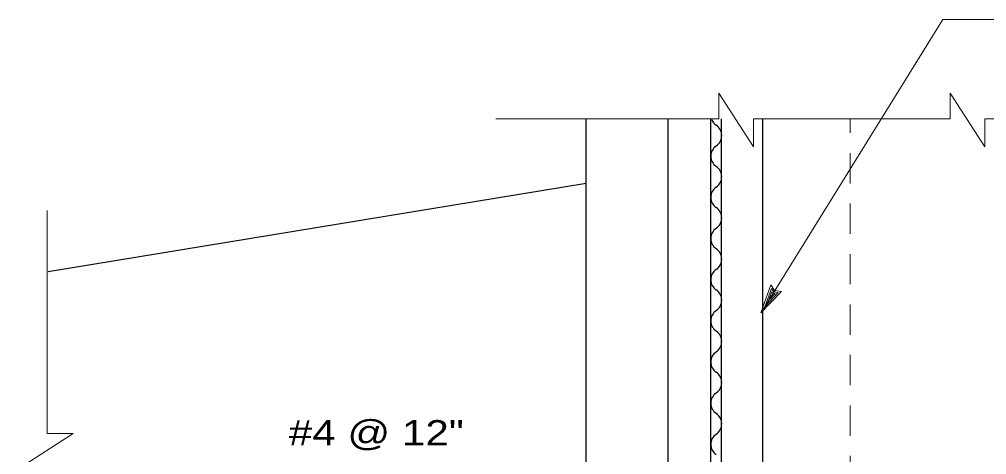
# Model space of a CAD drawing. Extents: x -28.1 to 13.9, y -16.1 to 13.9.
# Drawn here: x -24.101 to -19.308, y -3.215 to -1.058 of the extents above; entities that cross this region are included whole.
import ezdxf
from ezdxf.enums import TextEntityAlignment as Align

# ---------------------------------------------------------------- set-up
doc = ezdxf.new("R2010")
doc.units = 0
doc.header["$LTSCALE"] = 0.05
doc.linetypes.add('MEDIUM_DASHED', pattern=[4.5, 3, -1.5])
doc.layers.add('1', color=7, linetype='Continuous', lineweight=13)

msp = doc.modelspace()

# ---------------------------------------------------------------- linework, layer by layer
at = {"layer": '1'}
for p, q in [((-20.63504, -1.55131), (-20.63504, -1.42331)), ((-20.46304, -1.68931), (-20.63504, -1.42331)), ((-19.48904, -1.55131), (-19.48904, -1.42331)), ((-19.31704, -1.68931), (-19.48904, -1.42331)), ((-20.63504, -1.55131), (-21.74004, -1.55131)), ((-20.46304, -1.68931), (-20.46304, -1.55131)), ((-19.48904, -1.55131), (-20.46304, -1.55131)), ((-19.31704, -1.68931), (-19.31704, -1.55131)), ((-18.25304, -1.55131), (-19.31704, -1.55131)), ((-23.96304, -3.11031), (-23.96304, -2.00531)), ((-20.42704, -2.51331), (-20.37804, -2.37431)), ((-20.40804, -2.48231), (-20.37504, -2.39131)), ((-20.37504, -2.39131), (-20.36304, -2.40931)), ((-20.42704, -2.51331), (-20.32504, -2.40731)), ((-20.40804, -2.48231), (-20.34104, -2.41231)), ((-20.38904, -2.45131), (-20.37304, -2.40731)), ((-20.38904, -2.45131), (-20.35704, -2.41731)), ((-20.37304, -2.40731), (-20.36704, -2.41631)), ((-20.36704, -2.41631), (-20.35704, -2.41731)), ((-20.36304, -2.40931), (-20.34104, -2.41231)), ((-24.10104, -3.28231), (-23.83504, -3.11031)), ((-23.96304, -3.11031), (-23.83504, -3.11031))]:
    msp.add_line(p, q, dxfattribs=at)
at = {"layer": '1', "lineweight": 25}
for p, q in [((-21.29204, -4.96431), (-21.29204, -1.55131)), ((-20.88704, -4.84331), (-20.88704, -1.55131)), ((-20.67504, -4.84331), (-20.67504, -1.55131)), ((-20.62204, -4.84331), (-20.62204, -1.55131)), ((-20.41804, -4.84331), (-20.41804, -1.55131)), ((-23.95804, -2.30831), (-21.29204, -1.87031))]:
    msp.add_line(p, q, dxfattribs=at)
at = {"layer": '1', "linetype": 'MEDIUM_DASHED'}
msp.add_line((-19.98404, -4.62131), (-19.98404, -1.55031), dxfattribs=at)
at = {"layer": '1'}
for points in [[(-20.42404, -2.50931), (-19.52504, -1.05831), (-19.25104, -1.05831)], [(-20.37804, -2.37431), (-20.35904, -2.40231), (-20.32504, -2.40731)]]:
    msp.add_lwpolyline(points, dxfattribs=at)
at = {"layer": '1', "lineweight": 25}
for centre, start, end in [((-20.61354, -1.53231), 201.80141, 235.92281), ((-20.68254, -1.63431), 304.0772, 55.92281), ((-20.61354, -1.73631), 124.0772, 235.92281), ((-20.68254, -1.83831), 304.0772, 55.92281), ((-20.61354, -1.94031), 124.0772, 235.92281), ((-20.68254, -2.04231), 304.0772, 55.92281), ((-20.61354, -2.14431), 124.0772, 235.92281), ((-20.68254, -2.24631), 304.0772, 55.92281), ((-20.61354, -2.34831), 124.0772, 235.92281), ((-20.68254, -2.45031), 304.0772, 55.92281), ((-20.61354, -2.55231), 124.0772, 235.92281), ((-20.68254, -2.65431), 304.0772, 55.92281), ((-20.61354, -2.75631), 124.0772, 235.92281), ((-20.68254, -2.85831), 304.0772, 55.92281), ((-20.61354, -2.96031), 124.0772, 235.92281), ((-20.68254, -3.06231), 304.0772, 55.92281), ((-20.61354, -3.16431), 124.0772, 235.92281)]:
    msp.add_arc(centre, 0.06157, start, end, dxfattribs=at)

# ---------------------------------------------------------------- texts
at = {"layer": '1', "width": 1.25}
msp.add_text('#4 @ 12"', height=0.125, dxfattribs=at).set_placement((-22.33248, -3.16931), align=Align.CENTER)

doc.saveas('drawing.dxf')
